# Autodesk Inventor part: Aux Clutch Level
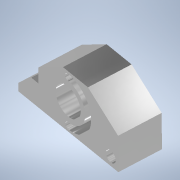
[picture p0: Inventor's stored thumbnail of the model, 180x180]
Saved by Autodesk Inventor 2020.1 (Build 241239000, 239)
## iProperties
Created: 2014-11
Part Number: Aux Clutch Level
Material: Steel
Document SubType Name: Modeling
Designer: Prachaya
Density: 7.85 g/cm^3
Appearance: Chrome - Polished
Mass: 801.585 g
Surface Area: 189.104 cm^2
Volume: 102.113 cm^3
Author: Prachaya
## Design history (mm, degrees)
sketch "Sketch1"
  geometry: L1 (0, 0)-(0, 7); L2 (0, 7)-(13, 20); L3 (13, 20)-(20, 20); L4 (20, 20)-(20, 32.92); L5 (20, 32.92)-(45, 50); L6 (45, 50)-(70, 50); L7 (70, 50)-(100, 30); L8 (100, 30)-(100, 0); L9 (100, 0)-(0, 0); C1 r 12.5 at (50, 25); C2 r 5 at (92.5, 8); A1 r 20 centre (50, 25) between (50, 5) and (50, 45); A2 r 23 centre (50, 25) between (50, 2) and (50, 48); A3 r 17 centre (50, 25) between (50, 8) and (50, 42); A4 r 3 centre (50, 5) between (50, 8) and (50, 2); A5 r 3 centre (50, 45) between (50, 48) and (50, 42)
  constraints: 18 end point, 10 point on circle, 7 centre point, 4 tangent, 2 horizontal, 2 perpendicular, 2 vertical, 2 vertical alignment, 1 coincident
  dimensions: "d0" = 7 distance of L1.start L1.end; "d2" = 20 vertical distance of L1.start L2.end; "d4" = 32.92 vertical distance of L1.start L4.end; "d6" = 50 vertical distance of L1.start L5.end; "d10" = 25 diameter of C1; "d11" = 25 distance from line of L9 C1.centre; "d12" = 50 distance from line of C1.centre L1; "d14" = 10 diameter of C2; "d15" = 8 distance from line of C2.centre L9; "d16" = 7.5 distance from line of C2.centre L8; "d28" = 13 horizontal distance of L1.end L2.end; "d29" = 20 distance between parallel lines of L1 L4; "d30" = 45 distance from line of L1 L5.end; "d31" = 70 horizontal distance of L1.start L6.end; "d32" = 100 distance between parallel lines of L1 L8; "d33" = 30 distance of L7.end L8.end; "d34" = 20 radius of A1; "d35" = 3 radius of A5
extrude "Extrusion1" new body sketch "Sketch1" distance "d17" = 35; taper "d18" = 0 deg
body "Solid1"
